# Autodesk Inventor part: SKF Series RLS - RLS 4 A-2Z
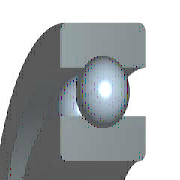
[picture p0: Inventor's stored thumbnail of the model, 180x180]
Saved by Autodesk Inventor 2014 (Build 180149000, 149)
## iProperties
IsCustomPart: 0
Created: 2008-02
Part Number: SKF Series RLS - RLS 4 A-2Z
Material: Steel, Mild
Description: Deep Groove Ball Bearings with Two Shields
Document SubType Name: Modeling
Standard: SKF Series RLS
Designer: tangg
Language: en-US
Size Designation: RLS 4 A-2Z
Categories: <MemberInstance><Categories><Category DisplayName="Shaft Parts" InternalName="7f7aeb1f-a693-4053-b835-cee3144e0d98" Mnemonic="SHFT"><Category DisplayName="Beari
Density: 7.86 g/cm^3
Mass: 36.4326 g
Surface Area: 44.4354 cm^2
Volume: 4.63519 cm^3
Appearance: Steel
Author: tangg
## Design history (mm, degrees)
node "Sketch1"
node "WorkPoint1"
node "WorkAxis1"
node "WorkPlane3"
node "WorkPlane4"
node "Sketch4"
node "WorkPoint2"
pattern_circular "PolarArray1" dims "d17" = 59.76923 (= msp_pocet), angle "d19" = 360 deg
fillet "Fillet1" dims "d20" = 0.79375 (= r)
body "Solid1"
revolve "Revolution1" stored, may be unused: angle "d6" = 360 deg
revolve "Revolution2" stored, may be unused: angle "d10" = 360 deg
revolve "Revolution3" stored, may be unused: angle "d16" = 360 deg
sketch "Sketch2"
  geometry: L1 (6.35, 9.525)-(16.669, 9.525); L2 (6.35, 0)-(6.35, 9.525); L3 (16.669, 0)-(6.35, 0); L4 (16.669, 9.525)-(16.669, 0); L5 (0, 0)-(0, 20); L6 (0, 0)-(0, 20); L7 (-3.334, 0)-(20.003, 0) reference
  constraints: 12 end point, 3 vertical, 2 horizontal, 1 collinear, 1 other
  dimensions: "d1" = 12.7 diameter of L1.start L5 (= Diam); "d3" = 33.3375 diameter of L1.end L5 (= DD); "d5" = 9.525 distance of L2.start L1.start (= msp_mdtd2)
sketch "Sketch3"
  geometry: L1 (13.367, 9.525)-(13.367, 7.239); L2 (9.652, 9.525)-(13.367, 9.525); L3 (9.652, 7.239)-(9.652, 9.525); L4 (9.652, 0)-(9.652, 2.286); L5 (13.367, 0)-(9.652, 0); L6 (13.367, 2.286)-(13.367, 0); L7 (16.669, 0)-(-16.669, 0) reference; L8 (16.669, 9.525)-(-16.669, 9.525) reference; L9 (0, -42.29)-(0, 61.29); L10 (0, 82.007)-(0, -63.007) reference; A1 r 3.096 centre (11.509, 4.763) between (13.367, 2.286) and (13.367, 7.239); A2 r 3.096 centre (11.509, 4.763) between (9.652, 7.239) and (9.652, 2.286)
  constraints: 14 end point, 4 collinear, 4 point on circle, 4 vertical, 2 centre point, 2 concentric, 2 horizontal, 2 point on line
  dimensions: "d9" = 6.19125 diameter of A1 (= msp_mdtd6); "d21" = 9.652 distance between parallel lines of L9 L4 (= 0.5 x msp_d1); "d22" = 11.50937 distance from line of L9 A1.centre (= 0.5 x msp_ds); "d23" = 13.36675 distance between parallel lines of L9 L6 (= 0.5 x msp_dd1)
sketch "Sketch5"
  geometry: L1 (11.509, 1.667)-(11.509, 7.858); L2 (13.367, 0)-(-13.367, 0) reference; L3 (11.509, 1.667)-(11.509, 7.858); A1 r 3.096 centre (11.509, 4.763) between (11.509, 1.667) and (11.509, 7.858); A2 r 3.096 centre (11.509, 4.763) between (13.367, 2.286) and (13.367, 7.239) reference
  constraints: 4 end point, 2 point on circle, 1 centre point, 1 concentric, 1 vertical
  dimensions: "d13" = 0 horizontal distance of A1.centre L1.start; "d15" = 6.19135 diameter of A1 (computed from msp_mdtd6)
other parameters: "Diam" = 12.7 [user parameter; used in 3 equation terms], "DD" = 33.3375 [user parameter; used in 3 equation terms], "B" = 9.525 [user parameter; used in 1 equation term], "r" = 0.79375 [user parameter; used in 1 equation term], "msp_ds" = 23.01875 (= 0.5 x Diam + 0.5 x DD) [user parameter; used in 5 equation terms], "msp_d0" = 6.19125 (= -0.3 x Diam + 0.3 x DD) [user parameter; used in 4 equation terms], "msp_d1" = 19.304 (= msp_ds - 0.6 x msp_d0) [user parameter; used in 1 equation term], "msp_dd1" = 26.7335 (= msp_ds + 0.6 x msp_d0) [user parameter; used in 1 equation term], "msp_pom" = 34.52813 (= 1.5 x msp_ds) [user parameter; used in 1 equation term], "msp_mdtd2" = 9.525 (= B) [user parameter; used in 3 equation terms], "msp_mdtd4" = 23.01875 (= msp_ds) [user parameter], "msp_mdtd6" = 6.19125 (= msp_d0) [user parameter; used in 2 equation terms], "msp_mdtd7" = 4.7625 (= 0.5 x msp_mdtd2) [user parameter], "msp_pocet" = 59.76923 (computed from msp_d0, msp_pom) [user parameter; used in 1 equation term], "d2" = 72 (derived), "d4" = 19 (derived), "d7" = 0, "d8" = 15.6 (derived), "d11" = -9.525 (computed from msp_mdtd2), "d12" = 0 (derived), "d14" = 15.6001 (derived), "d26" = 0, "d31" = 0, "d32" = 0, "d33" = 0, "d34" = 0
